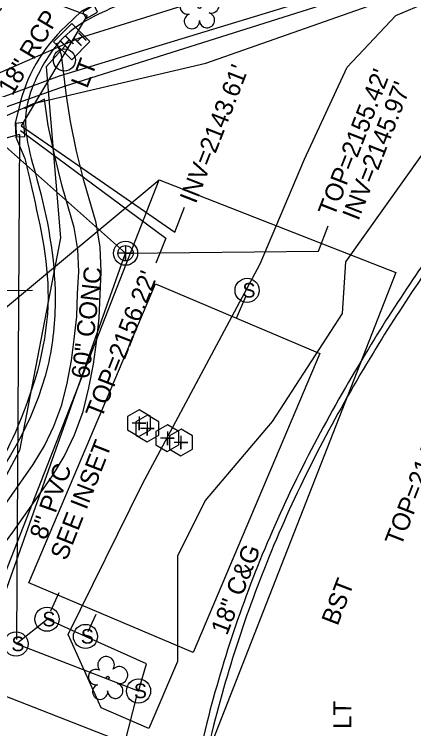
# Model space of a CAD drawing. Extents: x 945964 to 948456, y 631061 to 636061.
# Drawn here: x 946395.5 to 946484.6, y 632540.1 to 632699.5 of the extents above; entities that cross this region are included whole.
import ezdxf

# ---------------------------------------------------------------- set-up
doc = ezdxf.new("R2010")
doc.units = 0
for name, color, linetype in [('Default', 7, 'Continuous'), ('Exist Other Culture Area Outline', 7, 'Continuous'), ('Exist Other Culture Gate', 7, 'Continuous'), ('Exist Roads Curbs', 7, 'Continuous'), ('Exist Roads Curbs Text', 7, 'Continuous'), ('Exist Roads EOP', 7, 'Continuous'), ('Exist Roads EOP Other', 7, 'Continuous'), ('Exist Roads EOP Other Text', 7, 'Continuous'), ('Exist Structure Minor Catch Basin', 7, 'Continuous'), ('Exist Structure Minor Catch Basin Top Elevation', 7, 'Continuous'), ('Exist Structure Minor Pipes HDPE 12 Inch', 7, 'Continuous'), ('Exist Structure Minor Pipes HDPE 24 Inch', 7, 'Continuous'), ('Exist Structure Minor Pipes RCP 18 Inch', 7, 'Continuous'), ('Exist Structure Minor Pipes RCP 18 Inch Invert', 7, 'Continuous'), ('Exist Structure Minor Pipes RCP 18 Inch Text', 7, 'Continuous'), ('Exist Structure Minor Storm Sewer Manhole CELL', 7, 'Continuous'), ('Exist Utilities Gas UG Line SUE', 7, 'Continuous'), ('Exist Utilities Other Pole CELL', 7, 'Continuous'), ('Exist Utilities Other Pole Text', 7, 'Continuous'), ('Exist Utilities Power Hand Hole CELL', 7, 'Continuous'), ('Exist Utilities Power UG Cable SUE', 7, 'Continuous'), ('Exist Utilities Sanitary Sewer Clean-Out CELL', 7, 'Continuous'), ('Exist Utilities Sanitary Sewer Manhole CELL', 7, 'Continuous'), ('Exist Utilities Sanitary Sewer Manhole Top Elevation', 7, 'Continuous'), ('Exist Utilities Sanitary Sewer UG Line', 7, 'Continuous'), ('Exist Utilities Sanitary Sewer UG Line Invert Elevation', 7, 'Continuous'), ('Exist Utilities Sanitary Sewer UG Line Text', 7, 'Continuous'), ('Exist Utilities Telephone UG Cable SUE', 7, 'Continuous'), ('Exist Vegetation Hedge Row', 7, 'Continuous'), ('Exist Vegetation Tree CELL', 7, 'Continuous')]:
    doc.layers.add(name, color=color, linetype=linetype)

# ---------------------------------------------------------------- blocks, each defined once
blk = doc.blocks.new('EXIST UTILITIES POWER HAND HOLE')
at = {"layer": 'Exist Utilities Power Hand Hole CELL'}
blk.add_line((0, 0), (0, 0), dxfattribs=at)
blk.add_lwpolyline([(-0.059, -0.0545), (0.056, -0.0545), (0.056, 0.0605), (-0.059, 0.0605), (-0.059, -0.0545)], dxfattribs=at)
for p in [(-0.0432, -0.0095), (0.0081, -0.0399)]:
    blk.add_text('H', height=0.05, dxfattribs=at).set_placement(p)
blk = doc.blocks.new('EXIST UTILITIES SANITARY SEWER CLEAN-OUT')
at = {"layer": 'Exist Utilities Sanitary Sewer Clean-Out CELL'}
blk.add_line((0, 0), (0, 0), dxfattribs=at)
blk.add_lwpolyline([(-0.0516, 0.0299), (-0.0517, -0.0297), (-0.0001, -0.0596), (0.0516, -0.0299), (0.0517, 0.0297), (0.0001, 0.0596)], close=True, dxfattribs=at)
blk.add_lwpolyline([(0, 0.0302), (0, -0.0302), (0, 0), (0.0302, 0), (-0.0302, 0)], dxfattribs=at)
blk = doc.blocks.new('EXIST STRUCTURE MINOR STORM SEWER MANHOLE')
at = {"layer": 'Exist Structure Minor Storm Sewer Manhole CELL'}
blk.add_circle((0, 0), 0.0539, dxfattribs=at)
blk.add_text('S', height=0.065, dxfattribs=at).set_placement((-0.0206, -0.032))
blk = doc.blocks.new('EXIST VEGETATION TREE')
at = {"layer": 'Exist Vegetation Tree CELL'}
blk.add_line((0, 0), (0, 0), dxfattribs=at)
blk.add_circle((0, 0), 0.00652, dxfattribs=at)
for centre, radius, start, end in [((-0.0077, 0.0575), 0.0371, 330.1651, 219.7134), ((-0.0521, 0.0031), 0.0345, 62.6636, 279.3457), ((0.051, 0.0118), 0.038, 257.1011, 134.1999), ((-0.0341, -0.0624), 0.0338, 111.5671, 6.231), ((0.0335, -0.058), 0.034, 181.2822, 74.56)]:
    blk.add_arc(centre, radius, start, end, dxfattribs=at)
blk = doc.blocks.new('EXIST UTILITIES OTHER POLE')
at = {"layer": 'Exist Utilities Other Pole CELL'}
blk.add_circle((0, 0), 0.0493, dxfattribs=at)
blk = doc.blocks.new('EXIST UTILITIES SANITARY SEWER MANHOLE')
at = {"layer": 'Exist Utilities Sanitary Sewer Manhole CELL'}
blk.add_lwpolyline([(0, 0.0342), (0, -0.0342), (0, 0), (0.0342, 0), (-0.0342, 0)], dxfattribs=at)
for radius in [0.0539, 0.0342]:
    blk.add_circle((0, 0), radius, dxfattribs=at)

msp = doc.modelspace()

# ---------------------------------------------------------------- linework, layer by layer
at = {"layer": 'Default'}
msp.add_line((946077.6, 632371.19), (946427.8, 632662.58), dxfattribs=at)
msp.add_lwpolyline([(946384.14, 632551.07), (946427.8, 632662.58), (946480.63, 632641.9), (946436.98, 632530.39)], close=True, dxfattribs=at)
at = {"layer": 'Exist Other Culture Area Outline'}
msp.add_lwpolyline([(946398.76, 632572.66), (946427.04, 632639.4), (946463.69, 632623.87), (946435.4, 632557.13)], close=True, dxfattribs=at)
at = {"layer": 'Exist Other Culture Gate'}
msp.add_lwpolyline([(946375.66, 632637.64), (946399.56, 632637.93)], dxfattribs=at)
at = {"layer": 'Exist Roads Curbs'}
for points in [[(946601.93, 632772.67), (946579.15, 632743.42), (946547.53, 632710.06), (946519.46, 632682.69), (946496.47, 632656.95), (946474.49, 632624.89), (946453.03, 632584.16), (946438.45, 632541.43), (946430.15, 632490.73), (946428.83, 632457.38), (946430.2, 632433.68), (946432.57, 632412.52), (946425.74, 632395.61), (946417.04, 632384.69)], [(946443.29, 632709.94), (946418.6, 632701.43), (946405.91, 632693.72), (946402.27, 632688.72), (946400.06, 632684.45), (946398.16, 632678.07), (946398.29, 632672.08), (946400.56, 632662.72), (946404.62, 632636.22), (946402.97, 632621.07), (946384.84, 632587.17), (946377.39, 632579.37), (946368.81, 632574.06)]]:
    msp.add_spline(points, degree=3, dxfattribs=at)
at = {"layer": 'Exist Roads EOP'}
for points in [[(946550.72, 632747.33), (946538.92, 632743.34), (946534.18, 632742.6), (946531.1, 632741.53), (946526.64, 632739.08), (946484.59, 632725.12), (946442.49, 632711.17), (946418.22, 632702.92), (946413.45, 632701.7), (946410.52, 632700.21), (946407.04, 632696.87)], [(946396.53, 632678.53), (946395.68, 632675.21), (946395.84, 632672.07), (946397.87, 632667.37)]]:
    msp.add_lwpolyline(points, dxfattribs=at)
msp.add_ellipse((946430.74, 632671.21), major_axis=(-34.7, 4.44), ratio=0.996419, start_param=5.583639, end_param=6.199441, dxfattribs=at)
for points in [[(946603.2, 632771.71), (946580.04, 632742.14), (946547.72, 632708.15), (946520.62, 632681.67), (946497.88, 632656.28), (946475.52, 632623.93), (946454.54, 632583.75), (946439.95, 632540.86), (946431.6, 632490.76), (946430.35, 632457.42), (946431.68, 632434.16), (946433.99, 632412.2), (946427.3, 632395.46), (946417.68, 632383.18)], [(946397.87, 632667.37), (946399.03, 632662.29), (946403.03, 632636.24), (946396.32, 632607.64), (946383.81, 632588.84), (946381.65, 632587.09), (946379.37, 632584.76), (946376.3, 632580.56), (946368.2, 632575.54)]]:
    msp.add_spline(points, degree=3, dxfattribs=at)
at = {"layer": 'Exist Roads EOP Other'}
for points in [[(946407.17, 632681.31), (946406.01, 632690.46), (946404.97, 632693.09)], [(946371.03, 632565.01), (946373.45, 632569.2), (946376.93, 632572.92), (946380.79, 632575.69), (946384.34, 632578.85), (946388, 632582.71), (946391.15, 632586.94), (946399.72, 632599.07), (946402.25, 632603.2), (946404.34, 632607.63), (946406.12, 632612.37), (946407.28, 632617.21), (946408.24, 632622.27), (946408.85, 632627), (946409.45, 632632.08), (946409.63, 632637.21), (946409.91, 632642.13), (946409.65, 632647.02), (946408.85, 632651.91), (946406.22, 632661.16), (946404.54, 632667.86), (946403.1, 632674.71), (946402.22, 632680.57)], [(946375.36, 632562.51), (946377.49, 632566.21), (946380.24, 632569.14), (946383.92, 632571.78), (946387.83, 632575.26), (946391.83, 632579.48), (946395.2, 632584), (946403.9, 632596.32), (946406.66, 632600.83), (946408.95, 632605.68), (946410.91, 632610.9), (946412.17, 632616.17), (946413.18, 632621.49), (946413.81, 632626.39), (946414.44, 632631.69), (946414.63, 632636.97), (946414.92, 632642.12), (946414.63, 632647.55), (946413.74, 632653), (946411.05, 632662.45), (946409.41, 632668.98), (946408.02, 632675.59), (946407.17, 632681.31)], [(946402.22, 632680.57), (946397.81, 632678.42)]]:
    msp.add_lwpolyline(points, dxfattribs=at)
at = {"layer": 'Exist Structure Minor Catch Basin'}
for points in [[(946413.33, 632701.52), (946410.83, 632700.01), (946411.57, 632698.55), (946414.09, 632699.99), (946413.33, 632701.52)], [(946395.82, 632675.18), (946395.96, 632672.18), (946397.89, 632672.28), (946397.61, 632675.34), (946395.82, 632675.18)]]:
    msp.add_lwpolyline(points, dxfattribs=at)
at = {"layer": 'Exist Structure Minor Catch Basin Top Elevation'}
msp.add_lwpolyline([(946396.91, 632673.6), (946429.3, 632649.54), (946427.11, 632643.95)], dxfattribs=at)
at = {"layer": 'Exist Structure Minor Pipes HDPE 12 Inch'}
msp.add_lwpolyline([(946423.22, 632548.54), (946425.03, 632554.62), (946411.39, 632560.71)], dxfattribs=at)
at = {"layer": 'Exist Structure Minor Pipes HDPE 24 Inch'}
for points in [[(946447.05, 632636.44), (946444.99, 632631.67)], [(946403.65, 632566.4), (946405.53, 632570.49)], [(946411.99, 632561.84), (946413.77, 632565.68)], [(946395.9, 632559.03), (946402.81, 632564.56)], [(946411.39, 632560.71), (946402.81, 632564.56)]]:
    msp.add_lwpolyline(points, dxfattribs=at)
at = {"layer": 'Exist Structure Minor Pipes RCP 18 Inch'}
for p, q in [((946411.74, 632699.25), (946397.05, 632674.65)), ((946396.7, 632672.66), (946395.97, 632560.02)), ((946403.14, 632469.16), (946422.91, 632547.69))]:
    msp.add_line(p, q, dxfattribs=at)
msp.add_lwpolyline([(946423.22, 632548.54), (946395.9, 632559.03)], dxfattribs=at)
at = {"layer": 'Exist Structure Minor Pipes RCP 18 Inch Invert'}
for points in [[(946411.74, 632699.25), (946394.45, 632705.86), (946392.27, 632700.27)], [(946397.05, 632674.65), (946431.33, 632650.9), (946433.51, 632656.49)], [(946396.7, 632672.66), (946384.32, 632669.33), (946382.13, 632663.74)]]:
    msp.add_lwpolyline(points, dxfattribs=at)
at = {"layer": 'Exist Utilities Gas UG Line SUE'}
msp.add_lwpolyline([(946328.8, 632353.04), (946373.09, 632367.86), (946390.79, 632374.2), (946416.26, 632409.78), (946398.86, 632469.97), (946389.31, 632500.41), (946363.99, 632571.54), (946360.18, 632599.46), (946347.82, 632660.28), (946348.31, 632668.93), (946363.39, 632670.11), (946405.63, 632685.78), (946486.74, 632710.56), (946558.09, 632746.02), (946590.61, 632771.11), (946619.22, 632810.2), (946619.67, 632824.44), (946594.97, 632905.61)], dxfattribs=at)
at = {"layer": 'Exist Utilities Power UG Cable SUE'}
for points in [[(946360.13, 632660.61), (946366.34, 632669.16), (946406.95, 632683.52), (946473.64, 632704.64), (946529.01, 632723.91), (946572.73, 632752.79), (946602.05, 632778.83), (946632.04, 632830.29), (946638.92, 632863.65), (946639.32, 632905.11), (946627.59, 632976.28), (946631.01, 632982.04)], [(946358.83, 632671.87), (946409.81, 632694.19), (946491.07, 632719.59), (946512.34, 632726.76), (946527.94, 632732.44), (946563.12, 632750.98), (946591.54, 632775.57), (946597.73, 632780.43), (946610.71, 632793.64), (946619, 632807.83), (946625.48, 632824.38), (946631.48, 632842.49), (946635.14, 632865.8), (946629.47, 632896.55)], [(946406.88, 632692.5), (946402.59, 632687.82), (946405.81, 632649.62), (946396.7, 632602.2), (946388.88, 632587.69)]]:
    msp.add_lwpolyline(points, dxfattribs=at)
at = {"layer": 'Exist Utilities Sanitary Sewer Manhole Top Elevation'}
msp.add_lwpolyline([(946420.33, 632646.2), (946463.34, 632646.7), (946465.53, 632652.29)], dxfattribs=at)
at = {"layer": 'Exist Utilities Sanitary Sewer UG Line'}
msp.add_lwpolyline([(946402.92, 632479.56), (946384.25, 632544.62), (946420.33, 632646.2), (946327.9, 632728.4)], dxfattribs=at)
at = {"layer": 'Exist Utilities Telephone UG Cable SUE'}
msp.add_lwpolyline([(946359.71, 632661.63), (946399.78, 632679.58), (946438.25, 632688.61), (946513.39, 632715.06), (946554.62, 632735.94), (946609.33, 632779.21), (946641.07, 632799.75), (946626.79, 632844.16), (946603.53, 632869.47), (946569.01, 632976.01), (946560.85, 632993.4), (946550.79, 632988.99)], dxfattribs=at)
at = {"layer": 'Exist Vegetation Hedge Row'}
msp.add_lwpolyline([(946508.23, 632698.85), (946469.4, 632644.26), (946468.63, 632632.76), (946453.01, 632608.66), (946438.09, 632591.02), (946431.9, 632578.64), (946431.93, 632555.16), (946425.49, 632540.17), (946414.91, 632544.82), (946407.52, 632561.16), (946424.07, 632594.79), (946450.38, 632643.82), (946460.27, 632667.16), (946469.78, 632687.73), (946480.6, 632699.26), (946493.29, 632704.68), (946502.78, 632708.02), (946508.13, 632698.23)], dxfattribs=at)

# ---------------------------------------------------------------- block references
at = {"layer": 'Exist Structure Minor Storm Sewer Manhole CELL', "xscale": 50, "yscale": 50}
for p in [(946447.44, 632637.92), (946402.81, 632564.56), (946411.39, 632560.71), (946395.9, 632559.03), (946423.22, 632548.54)]:
    msp.add_blockref('EXIST STRUCTURE MINOR STORM SEWER MANHOLE', p, dxfattribs=at)
at = {"layer": 'Exist Utilities Other Pole CELL', "xscale": 50, "yscale": 50}
msp.add_blockref('EXIST UTILITIES OTHER POLE', (946406.69, 632689.3), dxfattribs=at)
at = {"layer": 'Exist Utilities Power Hand Hole CELL', "xscale": 49.999999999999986, "yscale": 49.999999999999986, "rotation": 45.14757837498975}
msp.add_blockref('EXIST UTILITIES POWER HAND HOLE', (946408.49, 632693.35), dxfattribs=at)
at = {"layer": 'Exist Utilities Sanitary Sewer Clean-Out CELL', "xscale": 50, "yscale": 50}
for p in [(946423.33, 632608.27), (946425.18, 632607.08), (946429.65, 632604.93), (946432.69, 632603.98)]:
    msp.add_blockref('EXIST UTILITIES SANITARY SEWER CLEAN-OUT', p, dxfattribs=at)
at = {"layer": 'Exist Utilities Sanitary Sewer Manhole CELL', "xscale": 50, "yscale": 50}
msp.add_blockref('EXIST UTILITIES SANITARY SEWER MANHOLE', (946420.33, 632646.2), dxfattribs=at)
at = {"layer": 'Exist Vegetation Tree CELL', "xscale": 50, "yscale": 50}
for p in [(946436.82, 632701.09), (946416.36, 632551.49)]:
    msp.add_blockref('EXIST VEGETATION TREE', p, dxfattribs=at)

# ---------------------------------------------------------------- texts
at = {"layer": 'Default'}
msp.add_text('SEE INSET', height=4, rotation=68.6189, dxfattribs=at).set_placement((946407.14, 632577.44))
at = {"layer": 'Exist Roads Curbs Text'}
msp.add_text('18" C&G', height=4, rotation=68.8391, dxfattribs=at).set_placement((946442.95, 632560.77))
at = {"layer": 'Exist Roads EOP Other Text'}
for s, rotation, p in [('60" CONC', 83.2654, (946412.19, 632618.06)), ('BST', 68.935, (946467.62, 632562.92))]:
    msp.add_text(s, height=4, rotation=rotation, dxfattribs=at).set_placement(p)
at = {"layer": 'Exist Structure Minor Catch Basin Top Elevation'}
for s, p in [("TOP=2156.22'", (946414.98, 632609.14)), ("TOP=2149.55'", (946481.76, 632580.63))]:
    msp.add_text(s, height=4, rotation=68.6189, dxfattribs=at).set_placement(p)
at = {"layer": 'Exist Structure Minor Pipes RCP 18 Inch Invert'}
msp.add_text("INV=2143.61'", height=4, rotation=68.6189, dxfattribs=at).set_placement((946435.99, 632657.07))
at = {"layer": 'Exist Structure Minor Pipes RCP 18 Inch Text'}
msp.add_text('18" RCP', height=4, rotation=59.1616, dxfattribs=at).set_placement((946395.07, 632681.16))
at = {"layer": 'Exist Utilities Other Pole Text'}
for rotation, p in [(68.619, (946411.75, 632682.78)), (89.5187, (946470.65, 632540.07))]:
    msp.add_text('LT', height=4, rotation=rotation, dxfattribs=at).set_placement(p)
at = {"layer": 'Exist Utilities Sanitary Sewer Manhole Top Elevation'}
msp.add_text("TOP=2155.42'", height=4, rotation=68.6189, dxfattribs=at).set_placement((946466.85, 632654.16))
at = {"layer": 'Exist Utilities Sanitary Sewer UG Line Invert Elevation'}
msp.add_text("INV=2145.97'", height=4, rotation=68.6189, dxfattribs=at).set_placement((946472.25, 632653.28))
at = {"layer": 'Exist Utilities Sanitary Sewer UG Line Text'}
msp.add_text('8" PVC', height=4, rotation=70.4438, dxfattribs=at).set_placement((946402.56, 632582.04))

doc.saveas('drawing.dxf')
